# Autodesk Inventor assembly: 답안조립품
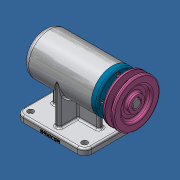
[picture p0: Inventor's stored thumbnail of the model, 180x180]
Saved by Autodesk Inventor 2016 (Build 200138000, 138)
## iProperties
Created: 2020-10
Part Number: 답안조립품
Material: 일반
Document SubType Name: Assembly
Designer: 605-11
Author: 605-11
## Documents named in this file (12)
- C:\Users\605-11\Desktop\701004V1005\답안조립품.iam
- C:\Users\605-11\Desktop\701004V1005\1.본체.ipt
- C:\Users\605-11\Desktop\701004V1005\축.ipt
- C:\Users\605-11\Desktop\701004V1005\베어링 6004.ipt
- C:\Users\605-11\Desktop\701004V1005\어댑터슬리브.ipt
- C:\Users\605-11\Desktop\701004V1005\볼트 M4.ipt
- C:\Users\605-11\Desktop\701004V1005\베어링 51202.ipt
- C:\Users\605-11\Desktop\701004V1005\커버.ipt
- C:\Users\605-11\Desktop\701004V1005\오일 실.ipt
- C:\Users\605-11\Desktop\701004V1005\V벨트풀리.ipt
- C:\Users\605-11\Desktop\701004V1005\키 5 x 5 x 16.ipt
- C:\Users\605-11\Desktop\701004V1005\멈춤나사 M3.ipt
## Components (2 placed, 2 different names)
1. 1.본체:1
2. V벨트풀리:1
